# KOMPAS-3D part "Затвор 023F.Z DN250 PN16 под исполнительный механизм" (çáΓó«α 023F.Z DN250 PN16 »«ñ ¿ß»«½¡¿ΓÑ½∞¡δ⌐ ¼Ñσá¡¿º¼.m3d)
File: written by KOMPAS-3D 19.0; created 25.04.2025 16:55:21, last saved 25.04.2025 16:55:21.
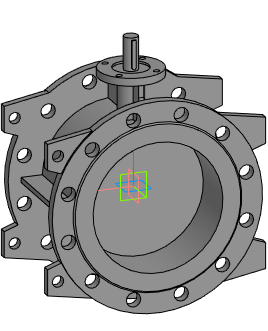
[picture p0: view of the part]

Document properties: Автор: Евгений; Полное имя файла: E:\Dendor Работа Сачек\3D для проекитирвщиков\1.7 Тип 023F.Z Затвор дисковый поворотный фланцевый с двумя эксцентриками\stp_Тип 023F.Z. Затвор под исполн. механизм\Затвор 023F.Z DN250 PN16 под исполнительный механизм.m3d

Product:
- Part/product: Затвор 023F.Z DN250 PN16 под исполнительный механизм

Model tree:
1. Операция без истории:1  (labels: Затвор 023F.Z DN250 PN16 под исполнительный механизм)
